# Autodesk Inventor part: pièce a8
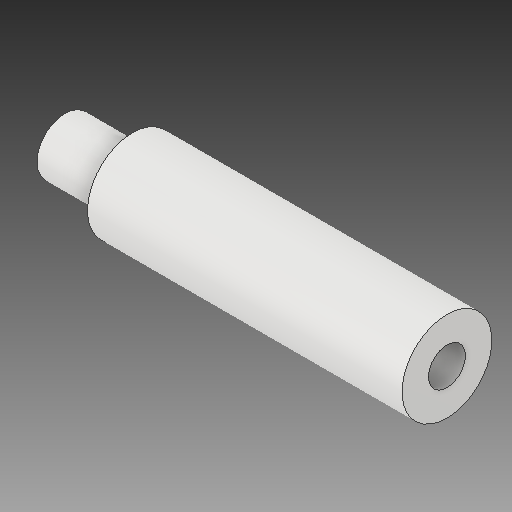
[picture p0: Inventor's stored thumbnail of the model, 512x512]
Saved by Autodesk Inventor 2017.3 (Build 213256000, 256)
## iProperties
Created: 2007-12
Part Number: pièce a8
Material: solidworks materials|Alliage 7079|22
Document SubType Name: Modeling
Designer: ficho
Appearance: 255,255,255
Author: ficho
Sending System: SolidWorks 2009
Last Author: christophe
Last Saved: 2011-02-10
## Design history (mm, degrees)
feature "Trou taraudé M41"
node "Solide1"
